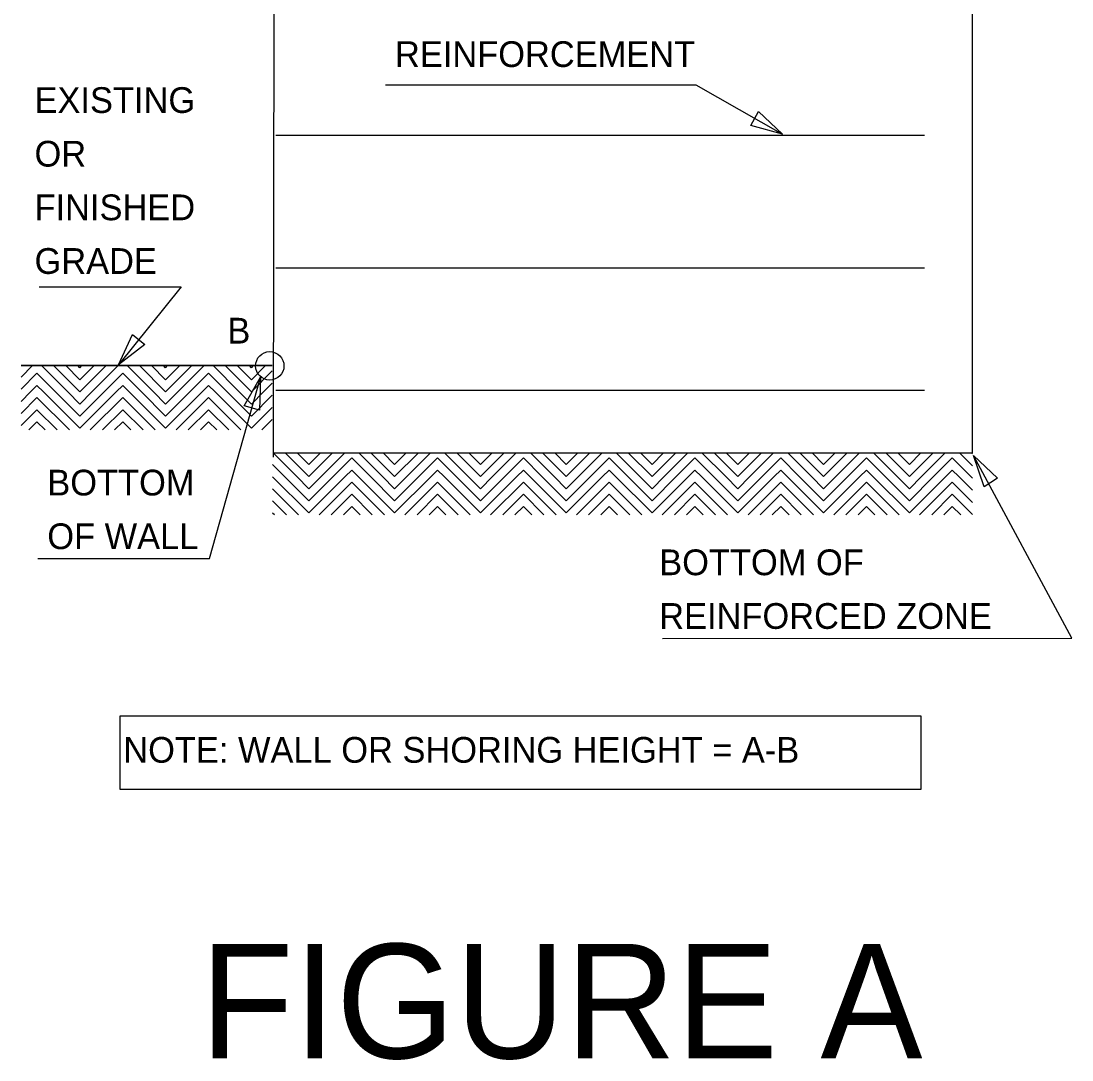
# Model space of a CAD drawing. Extents: x 2487012 to 2497594, y 369516 to 371986.
# Drawn here: x 2487367.6 to 2487624.9, y 370730.2 to 370984.4 of the extents above; entities that cross this region are included whole.
import ezdxf

# ---------------------------------------------------------------- set-up
doc = ezdxf.new("R2010")
doc.units = 0
for name, color, linetype in [('TC LABEL TEMP SHORING', 7, 'Continuous'), ('TC LABEL TEXT', 7, 'Continuous'), ('TC SHEET TEXT', 7, 'Continuous')]:
    doc.layers.add(name, color=color, linetype=linetype)

msp = doc.modelspace()

# ---------------------------------------------------------------- linework, layer by layer
at = {"layer": 'TC LABEL TEMP SHORING'}
for p, q in [((2487429.59, 371080.9), (2487429.28, 370877.67)), ((2487600.51, 370878.76), (2487600.51, 371082)), ((2487429.94, 370956.53), (2487588.75, 370956.53)), ((2487429.94, 370924.04), (2487588.75, 370924.04)), ((2487367.59, 370897.3), (2487370.4, 370900.1)), ((2487379.02, 370893.66), (2487372.59, 370900.1)), ((2487381.99, 370893.66), (2487375.56, 370900.1)), ((2487381.99, 370896.63), (2487378.53, 370900.1)), ((2487381.99, 370899.6), (2487381.5, 370900.1)), ((2487381.99, 370893.66), (2487388.43, 370900.1)), ((2487381.99, 370896.63), (2487385.46, 370900.1)), ((2487381.99, 370899.6), (2487382.49, 370900.1)), ((2487384.96, 370893.66), (2487391.4, 370900.1)), ((2487400.02, 370893.66), (2487393.59, 370900.1)), ((2487402.99, 370893.66), (2487396.56, 370900.1)), ((2487402.99, 370896.63), (2487399.53, 370900.1)), ((2487402.99, 370899.6), (2487402.5, 370900.1)), ((2487402.99, 370893.66), (2487409.43, 370900.1)), ((2487402.99, 370896.63), (2487406.46, 370900.1)), ((2487402.99, 370899.6), (2487403.49, 370900.1)), ((2487405.96, 370893.66), (2487412.4, 370900.1)), ((2487421.02, 370893.66), (2487414.59, 370900.1)), ((2487423.99, 370893.66), (2487417.56, 370900.1)), ((2487423.99, 370896.63), (2487420.53, 370900.1)), ((2487423.99, 370899.6), (2487423.5, 370900.1)), ((2487423.99, 370896.63), (2487427.46, 370900.1)), ((2487423.99, 370899.6), (2487424.49, 370900.1)), ((2487367.59, 370894.33), (2487371.49, 370898.22)), ((2487376.05, 370893.66), (2487371.49, 370898.22)), ((2487387.93, 370893.66), (2487392.49, 370898.22)), ((2487397.05, 370893.66), (2487392.49, 370898.22)), ((2487408.93, 370893.66), (2487413.49, 370898.22)), ((2487418.05, 370893.66), (2487413.49, 370898.22)), ((2487423.99, 370893.66), (2487429.11, 370898.79)), ((2487369.9, 370893.66), (2487371.49, 370895.26)), ((2487373.08, 370893.66), (2487371.49, 370895.26)), ((2487390.9, 370893.66), (2487392.49, 370895.26)), ((2487394.08, 370893.66), (2487392.49, 370895.26)), ((2487411.9, 370893.66), (2487413.49, 370895.26)), ((2487415.08, 370893.66), (2487413.49, 370895.26)), ((2487426.96, 370893.66), (2487429.11, 370895.82)), ((2487367.59, 370891.36), (2487369.9, 370893.66)), ((2487367.59, 370888.39), (2487371.49, 370892.29)), ((2487379.43, 370884.35), (2487371.49, 370892.29)), ((2487381.99, 370884.76), (2487373.08, 370893.66)), ((2487381.99, 370887.72), (2487376.05, 370893.66)), ((2487381.99, 370890.69), (2487379.02, 370893.66)), ((2487381.99, 370884.76), (2487390.9, 370893.66)), ((2487381.99, 370887.72), (2487387.93, 370893.66)), ((2487381.99, 370890.69), (2487384.96, 370893.66)), ((2487384.56, 370884.35), (2487392.49, 370892.29)), ((2487400.43, 370884.35), (2487392.49, 370892.29)), ((2487402.99, 370884.76), (2487394.08, 370893.66)), ((2487402.99, 370887.72), (2487397.05, 370893.66)), ((2487402.99, 370890.69), (2487400.02, 370893.66)), ((2487402.99, 370884.76), (2487411.9, 370893.66)), ((2487402.99, 370887.72), (2487408.93, 370893.66)), ((2487402.99, 370890.69), (2487405.96, 370893.66)), ((2487405.56, 370884.35), (2487413.49, 370892.29)), ((2487421.43, 370884.35), (2487413.49, 370892.29)), ((2487423.99, 370884.76), (2487415.08, 370893.66)), ((2487423.99, 370887.72), (2487418.05, 370893.66)), ((2487423.99, 370890.69), (2487421.02, 370893.66)), ((2487423.99, 370890.69), (2487426.96, 370893.66)), ((2487423.99, 370887.72), (2487429.11, 370892.85)), ((2487429.94, 370894.08), (2487588.75, 370894.08)), ((2487423.99, 370884.76), (2487429.11, 370889.88)), ((2487367.59, 370885.42), (2487371.49, 370889.32)), ((2487376.46, 370884.35), (2487371.49, 370889.32)), ((2487387.53, 370884.35), (2487392.49, 370889.32)), ((2487397.46, 370884.35), (2487392.49, 370889.32)), ((2487408.53, 370884.35), (2487413.49, 370889.32)), ((2487418.46, 370884.35), (2487413.49, 370889.32)), ((2487369.5, 370884.35), (2487371.49, 370886.35)), ((2487373.49, 370884.35), (2487371.49, 370886.35)), ((2487390.5, 370884.35), (2487392.49, 370886.35)), ((2487394.49, 370884.35), (2487392.49, 370886.35)), ((2487411.5, 370884.35), (2487413.49, 370886.35)), ((2487415.49, 370884.35), (2487413.49, 370886.35)), ((2487426.56, 370884.35), (2487429.11, 370886.91)), ((2487435.09, 370872.96), (2487429.29, 370878.76)), ((2487429.47, 370878.76), (2487600.51, 370878.76)), ((2487438.06, 370872.96), (2487432.26, 370878.76)), ((2487433.74, 370878.68), (2487433.66, 370878.76)), ((2487433.74, 370878.68), (2487433.66, 370878.76)), ((2487433.74, 370878.68), (2487433.81, 370878.76)), ((2487433.74, 370878.68), (2487433.81, 370878.76)), ((2487438.06, 370875.93), (2487435.23, 370878.76)), ((2487438.06, 370872.96), (2487443.86, 370878.76)), ((2487438.06, 370875.93), (2487440.89, 370878.76)), ((2487441.03, 370872.96), (2487446.83, 370878.76)), ((2487444, 370872.96), (2487448.56, 370877.52)), ((2487453.12, 370872.96), (2487448.56, 370877.52)), ((2487456.09, 370872.96), (2487450.29, 370878.76)), ((2487459.06, 370872.96), (2487453.26, 370878.76)), ((2487454.74, 370878.68), (2487454.66, 370878.76)), ((2487454.74, 370878.68), (2487454.66, 370878.76)), ((2487454.74, 370878.68), (2487454.81, 370878.76)), ((2487454.74, 370878.68), (2487454.81, 370878.76)), ((2487459.06, 370875.93), (2487456.23, 370878.76)), ((2487459.06, 370872.96), (2487464.86, 370878.76)), ((2487459.06, 370875.93), (2487461.89, 370878.76)), ((2487462.03, 370872.96), (2487467.83, 370878.76)), ((2487465, 370872.96), (2487469.56, 370877.52)), ((2487474.12, 370872.96), (2487469.56, 370877.52)), ((2487477.09, 370872.96), (2487471.29, 370878.76)), ((2487480.06, 370872.96), (2487474.26, 370878.76)), ((2487475.74, 370878.68), (2487475.66, 370878.76)), ((2487475.74, 370878.68), (2487475.66, 370878.76)), ((2487475.74, 370878.68), (2487475.81, 370878.76)), ((2487475.74, 370878.68), (2487475.81, 370878.76)), ((2487480.06, 370875.93), (2487477.23, 370878.76)), ((2487480.06, 370872.96), (2487485.86, 370878.76)), ((2487480.06, 370875.93), (2487482.89, 370878.76)), ((2487483.03, 370872.96), (2487488.83, 370878.76)), ((2487486, 370872.96), (2487490.56, 370877.52)), ((2487495.12, 370872.96), (2487490.56, 370877.52)), ((2487498.09, 370872.96), (2487492.29, 370878.76)), ((2487501.06, 370872.96), (2487495.26, 370878.76)), ((2487496.74, 370878.68), (2487496.66, 370878.76)), ((2487496.74, 370878.68), (2487496.66, 370878.76)), ((2487496.74, 370878.68), (2487496.81, 370878.76)), ((2487496.74, 370878.68), (2487496.81, 370878.76)), ((2487501.06, 370875.93), (2487498.23, 370878.76)), ((2487501.06, 370872.96), (2487506.86, 370878.76)), ((2487501.06, 370875.93), (2487503.89, 370878.76)), ((2487504.03, 370872.96), (2487509.83, 370878.76)), ((2487507, 370872.96), (2487511.56, 370877.52)), ((2487516.12, 370872.96), (2487511.56, 370877.52)), ((2487519.09, 370872.96), (2487513.29, 370878.76)), ((2487522.06, 370872.96), (2487516.26, 370878.76)), ((2487517.74, 370878.68), (2487517.66, 370878.76)), ((2487517.74, 370878.68), (2487517.66, 370878.76)), ((2487517.74, 370878.68), (2487517.81, 370878.76)), ((2487517.74, 370878.68), (2487517.81, 370878.76)), ((2487522.06, 370875.93), (2487519.23, 370878.76)), ((2487522.06, 370872.96), (2487527.86, 370878.76)), ((2487522.06, 370875.93), (2487524.89, 370878.76)), ((2487525.03, 370872.96), (2487530.83, 370878.76)), ((2487528, 370872.96), (2487532.56, 370877.52)), ((2487537.12, 370872.96), (2487532.56, 370877.52)), ((2487540.09, 370872.96), (2487534.29, 370878.76)), ((2487543.06, 370872.96), (2487537.26, 370878.76)), ((2487538.74, 370878.68), (2487538.66, 370878.76)), ((2487538.74, 370878.68), (2487538.66, 370878.76)), ((2487538.74, 370878.68), (2487538.81, 370878.76)), ((2487538.74, 370878.68), (2487538.81, 370878.76)), ((2487543.06, 370875.93), (2487540.23, 370878.76)), ((2487543.06, 370872.96), (2487548.86, 370878.76)), ((2487543.06, 370875.93), (2487545.89, 370878.76)), ((2487546.03, 370872.96), (2487551.83, 370878.76)), ((2487549, 370872.96), (2487553.56, 370877.52)), ((2487558.12, 370872.96), (2487553.56, 370877.52)), ((2487561.09, 370872.96), (2487555.29, 370878.76)), ((2487564.06, 370872.96), (2487558.26, 370878.76)), ((2487559.74, 370878.68), (2487559.66, 370878.76)), ((2487559.74, 370878.68), (2487559.66, 370878.76)), ((2487559.74, 370878.68), (2487559.81, 370878.76)), ((2487559.74, 370878.68), (2487559.81, 370878.76)), ((2487564.06, 370875.93), (2487561.23, 370878.76)), ((2487564.06, 370872.96), (2487569.86, 370878.76)), ((2487564.06, 370875.93), (2487566.89, 370878.76)), ((2487567.03, 370872.96), (2487572.83, 370878.76)), ((2487570, 370872.96), (2487574.56, 370877.52)), ((2487579.12, 370872.96), (2487574.56, 370877.52)), ((2487582.09, 370872.96), (2487576.29, 370878.76)), ((2487585.06, 370872.96), (2487579.26, 370878.76)), ((2487580.74, 370878.68), (2487580.66, 370878.76)), ((2487580.74, 370878.68), (2487580.66, 370878.76)), ((2487580.74, 370878.68), (2487580.81, 370878.76)), ((2487580.74, 370878.68), (2487580.81, 370878.76)), ((2487585.06, 370875.93), (2487582.23, 370878.76)), ((2487585.06, 370872.96), (2487590.86, 370878.76)), ((2487585.06, 370875.93), (2487587.89, 370878.76)), ((2487588.03, 370872.96), (2487593.83, 370878.76)), ((2487591, 370872.96), (2487595.56, 370877.52)), ((2487600.12, 370872.96), (2487595.56, 370877.52)), ((2487600.51, 370875.54), (2487597.29, 370878.76)), ((2487600.51, 370878.51), (2487600.26, 370878.76)), ((2487432.12, 370872.96), (2487429.19, 370875.89)), ((2487446.97, 370872.96), (2487448.56, 370874.55)), ((2487450.15, 370872.96), (2487448.56, 370874.55)), ((2487467.97, 370872.96), (2487469.56, 370874.55)), ((2487471.15, 370872.96), (2487469.56, 370874.55)), ((2487488.97, 370872.96), (2487490.56, 370874.55)), ((2487492.15, 370872.96), (2487490.56, 370874.55)), ((2487509.97, 370872.96), (2487511.56, 370874.55)), ((2487513.15, 370872.96), (2487511.56, 370874.55)), ((2487530.97, 370872.96), (2487532.56, 370874.55)), ((2487534.15, 370872.96), (2487532.56, 370874.55)), ((2487551.97, 370872.96), (2487553.56, 370874.55)), ((2487555.15, 370872.96), (2487553.56, 370874.55)), ((2487572.97, 370872.96), (2487574.56, 370874.55)), ((2487576.15, 370872.96), (2487574.56, 370874.55)), ((2487593.97, 370872.96), (2487595.56, 370874.55)), ((2487597.15, 370872.96), (2487595.56, 370874.55)), ((2487438.06, 370864.05), (2487429.19, 370872.92)), ((2487438.06, 370867.02), (2487432.12, 370872.96)), ((2487438.06, 370869.99), (2487435.09, 370872.96)), ((2487438.06, 370864.05), (2487446.97, 370872.96)), ((2487438.06, 370867.02), (2487444, 370872.96)), ((2487438.06, 370869.99), (2487441.03, 370872.96)), ((2487440.56, 370863.58), (2487448.56, 370871.58)), ((2487456.56, 370863.58), (2487448.56, 370871.58)), ((2487459.06, 370864.05), (2487450.15, 370872.96)), ((2487459.06, 370867.02), (2487453.12, 370872.96)), ((2487459.06, 370869.99), (2487456.09, 370872.96)), ((2487459.06, 370864.05), (2487467.97, 370872.96)), ((2487459.06, 370867.02), (2487465, 370872.96)), ((2487459.06, 370869.99), (2487462.03, 370872.96)), ((2487461.56, 370863.58), (2487469.56, 370871.58)), ((2487477.56, 370863.58), (2487469.56, 370871.58)), ((2487480.06, 370864.05), (2487471.15, 370872.96)), ((2487480.06, 370867.02), (2487474.12, 370872.96)), ((2487480.06, 370869.99), (2487477.09, 370872.96)), ((2487480.06, 370864.05), (2487488.97, 370872.96)), ((2487480.06, 370867.02), (2487486, 370872.96)), ((2487480.06, 370869.99), (2487483.03, 370872.96)), ((2487482.56, 370863.58), (2487490.56, 370871.58)), ((2487498.56, 370863.58), (2487490.56, 370871.58)), ((2487501.06, 370864.05), (2487492.15, 370872.96)), ((2487501.06, 370867.02), (2487495.12, 370872.96)), ((2487501.06, 370869.99), (2487498.09, 370872.96)), ((2487501.06, 370864.05), (2487509.97, 370872.96)), ((2487501.06, 370867.02), (2487507, 370872.96)), ((2487501.06, 370869.99), (2487504.03, 370872.96)), ((2487503.56, 370863.58), (2487511.56, 370871.58)), ((2487519.56, 370863.58), (2487511.56, 370871.58)), ((2487522.06, 370864.05), (2487513.15, 370872.96)), ((2487522.06, 370867.02), (2487516.12, 370872.96)), ((2487522.06, 370869.99), (2487519.09, 370872.96)), ((2487522.06, 370864.05), (2487530.97, 370872.96)), ((2487522.06, 370867.02), (2487528, 370872.96)), ((2487522.06, 370869.99), (2487525.03, 370872.96)), ((2487524.56, 370863.58), (2487532.56, 370871.58)), ((2487540.56, 370863.58), (2487532.56, 370871.58)), ((2487543.06, 370864.05), (2487534.15, 370872.96)), ((2487543.06, 370867.02), (2487537.12, 370872.96)), ((2487543.06, 370869.99), (2487540.09, 370872.96)), ((2487543.06, 370864.05), (2487551.97, 370872.96)), ((2487543.06, 370867.02), (2487549, 370872.96)), ((2487543.06, 370869.99), (2487546.03, 370872.96)), ((2487545.56, 370863.58), (2487553.56, 370871.58)), ((2487561.56, 370863.58), (2487553.56, 370871.58)), ((2487564.06, 370864.05), (2487555.15, 370872.96)), ((2487564.06, 370867.02), (2487558.12, 370872.96)), ((2487564.06, 370869.99), (2487561.09, 370872.96)), ((2487564.06, 370864.05), (2487572.97, 370872.96)), ((2487564.06, 370867.02), (2487570, 370872.96)), ((2487564.06, 370869.99), (2487567.03, 370872.96)), ((2487566.56, 370863.58), (2487574.56, 370871.58)), ((2487582.56, 370863.58), (2487574.56, 370871.58)), ((2487585.06, 370864.05), (2487576.15, 370872.96)), ((2487585.06, 370867.02), (2487579.12, 370872.96)), ((2487585.06, 370869.99), (2487582.09, 370872.96)), ((2487585.06, 370864.05), (2487593.97, 370872.96)), ((2487585.06, 370867.02), (2487591, 370872.96)), ((2487585.06, 370869.99), (2487588.03, 370872.96)), ((2487587.56, 370863.58), (2487595.56, 370871.58)), ((2487600.51, 370866.63), (2487595.56, 370871.58)), ((2487600.51, 370869.6), (2487597.15, 370872.96)), ((2487600.51, 370872.57), (2487600.12, 370872.96)), ((2487435.56, 370863.58), (2487429.19, 370869.95)), ((2487432.59, 370863.58), (2487429.19, 370866.98)), ((2487443.53, 370863.58), (2487448.56, 370868.61)), ((2487453.59, 370863.58), (2487448.56, 370868.61)), ((2487464.53, 370863.58), (2487469.56, 370868.61)), ((2487474.59, 370863.58), (2487469.56, 370868.61)), ((2487485.53, 370863.58), (2487490.56, 370868.61)), ((2487495.59, 370863.58), (2487490.56, 370868.61)), ((2487506.53, 370863.58), (2487511.56, 370868.61)), ((2487516.59, 370863.58), (2487511.56, 370868.61)), ((2487527.53, 370863.58), (2487532.56, 370868.61)), ((2487537.59, 370863.58), (2487532.56, 370868.61)), ((2487548.53, 370863.58), (2487553.56, 370868.61)), ((2487558.59, 370863.58), (2487553.56, 370868.61)), ((2487569.53, 370863.58), (2487574.56, 370868.61)), ((2487579.59, 370863.58), (2487574.56, 370868.61)), ((2487590.53, 370863.58), (2487595.56, 370868.61)), ((2487600.51, 370863.66), (2487595.56, 370868.61)), ((2487429.62, 370863.58), (2487429.19, 370864.01)), ((2487446.5, 370863.58), (2487448.56, 370865.64)), ((2487450.62, 370863.58), (2487448.56, 370865.64)), ((2487467.5, 370863.58), (2487469.56, 370865.64)), ((2487471.62, 370863.58), (2487469.56, 370865.64)), ((2487488.5, 370863.58), (2487490.56, 370865.64)), ((2487492.62, 370863.58), (2487490.56, 370865.64)), ((2487509.5, 370863.58), (2487511.56, 370865.64)), ((2487513.62, 370863.58), (2487511.56, 370865.64)), ((2487530.5, 370863.58), (2487532.56, 370865.64)), ((2487534.62, 370863.58), (2487532.56, 370865.64)), ((2487551.5, 370863.58), (2487553.56, 370865.64)), ((2487555.62, 370863.58), (2487553.56, 370865.64)), ((2487572.5, 370863.58), (2487574.56, 370865.64)), ((2487576.62, 370863.58), (2487574.56, 370865.64)), ((2487593.5, 370863.58), (2487595.56, 370865.64)), ((2487597.62, 370863.58), (2487595.56, 370865.64))]:
    msp.add_line(p, q, dxfattribs=at)
msp.add_lwpolyline([(2487367.59, 370900.1), (2487367.59, 370900.1), (2487429.11, 370900.1), (2487367.59, 370900.1)], close=True, dxfattribs=at)
at = {"layer": 'TC LABEL TEXT'}
for points in [[(2487456.84, 370968.8), (2487532.75, 370968.8), (2487554.03, 370956.7)], [(2487372.03, 370919.35), (2487406.77, 370919.35), (2487391.44, 370900.33)], [(2487371.71, 370852.9), (2487413.73, 370852.9), (2487426.23, 370897.21)], [(2487524.61, 370833.3), (2487624.87, 370833.41), (2487600.72, 370878.13)]]:
    msp.add_lwpolyline(points, dxfattribs=at)
for points in [[(2487548.16, 370962.31), (2487554.03, 370956.7), (2487546.21, 370958.88)], [(2487548.16, 370962.31), (2487554.03, 370956.7), (2487546.21, 370958.88)], [(2487397.92, 370905.23), (2487391.44, 370900.33), (2487394.85, 370907.7)], [(2487397.92, 370905.23), (2487391.44, 370900.33), (2487394.85, 370907.7)], [(2487397.92, 370905.23), (2487391.44, 370900.33), (2487394.85, 370907.7)], [(2487397.92, 370905.23), (2487391.44, 370900.33), (2487394.85, 370907.7)], [(2487422.2, 370890.26), (2487426.23, 370897.31), (2487425.99, 370889.2)], [(2487422.2, 370890.26), (2487426.23, 370897.31), (2487425.99, 370889.2)], [(2487603.34, 370870.45), (2487600.72, 370878.13), (2487606.65, 370872.58)], [(2487603.34, 370870.45), (2487600.72, 370878.13), (2487606.65, 370872.58)], [(2487391.75, 370796.45), (2487587.98, 370796.45), (2487587.98, 370814.3), (2487391.75, 370814.3)]]:
    msp.add_lwpolyline(points, close=True, dxfattribs=at)
msp.add_circle((2487428.49, 370900.04), 3.48, dxfattribs=at)

# ---------------------------------------------------------------- texts
for s, p in [('REINFORCEMENT', (2487459.14, 370973.17)), ('EXISTING', (2487370.9, 370961.93)), ('OR', (2487370.9, 370948.8)), ('FINISHED', (2487370.9, 370935.68)), ('GRADE', (2487370.9, 370922.55)), ('B', (2487418.12, 370905.5)), ('BOTTOM ', (2487374.03, 370868.33)), ('OF WALL', (2487374.03, 370855.2)), ('BOTTOM OF ', (2487523.82, 370848.82)), ('REINFORCED ZONE', (2487523.82, 370835.69)), ('NOTE: WALL OR SHORING HEIGHT = A-B', (2487392.63, 370802.93))]:
    msp.add_text(s, height=6.3, dxfattribs=at).set_placement(p)
at = {"layer": 'TC SHEET TEXT'}
msp.add_text('FIGURE A', height=28, dxfattribs=at).set_placement((2487411.45, 370730.6))

doc.saveas('drawing.dxf')
